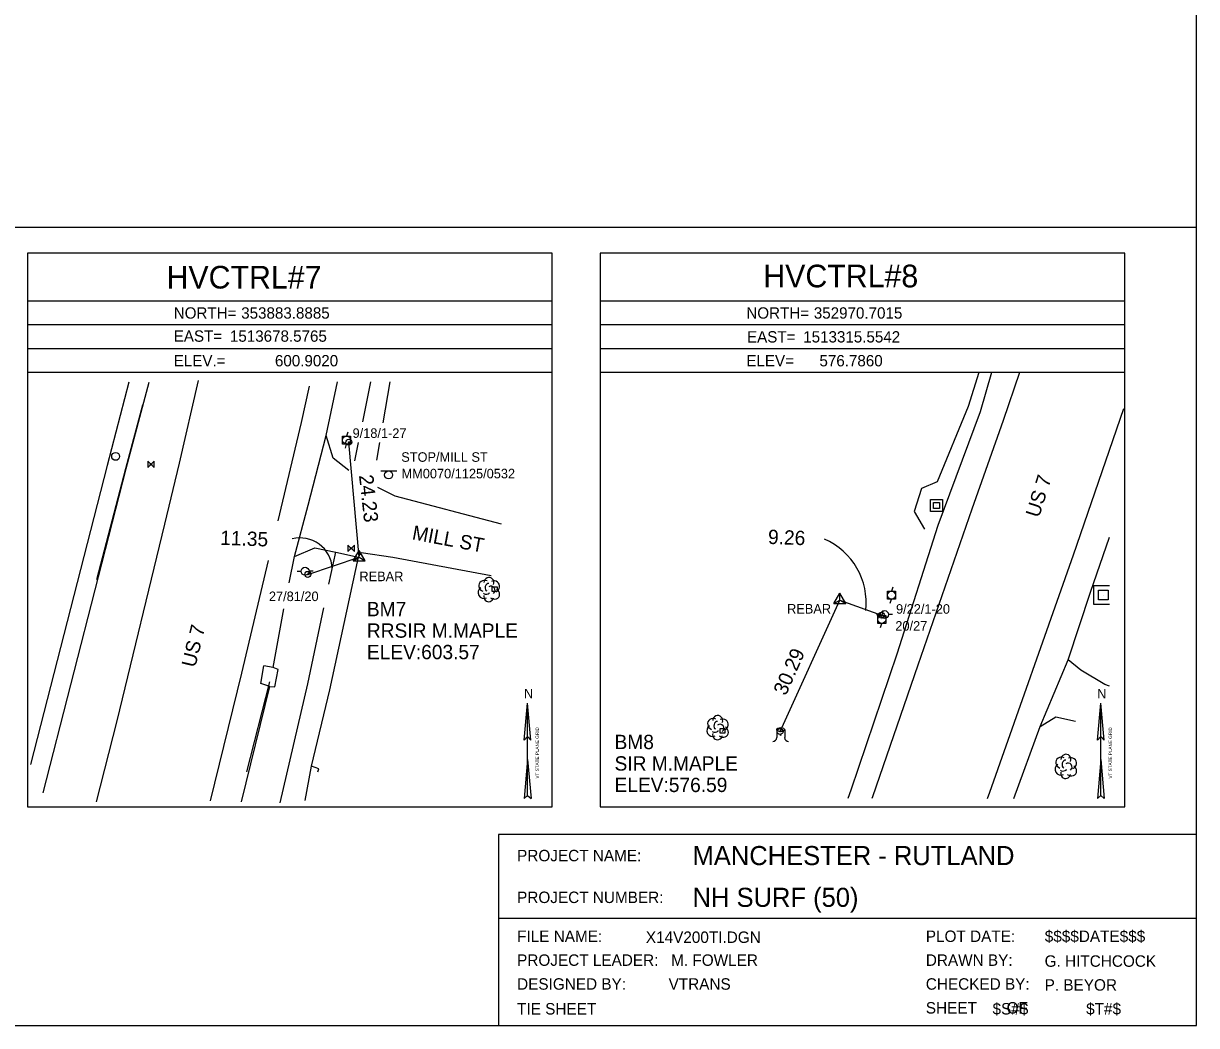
# Model space of a CAD drawing. Extents: x 1514039 to 1514679, y 870735 to 871155.
# Drawn here: x 1514432.7 to 1514678.6, y 870735.2 to 870945.2 of the extents above; entities that cross this region are included whole.
import ezdxf

# ---------------------------------------------------------------- set-up
doc = ezdxf.new("R2010")
doc.units = 0
for name, color, linetype in [('C_A', 7, 'Continuous'), ('CBP', 7, 'Continuous'), ('CPBM', 7, 'Continuous'), ('CPSM', 7, 'Continuous'), ('DCP', 7, 'Continuous'), ('Default', 7, 'Continuous'), ('DS', 7, 'Continuous'), ('LS', 7, 'Continuous'), ('LTD', 7, 'Continuous'), ('LTS', 7, 'Continuous'), ('NBL1', 7, 'Continuous'), ('NBL2', 7, 'Continuous'), ('NNA_P', 7, 'Continuous'), ('PET', 7, 'Continuous'), ('PSP', 7, 'Continuous'), ('RC', 7, 'Continuous'), ('RDP', 7, 'Continuous'), ('RSW', 7, 'Continuous'), ('S_C', 7, 'Continuous'), ('SSGN', 7, 'Continuous'), ('U_C', 7, 'Continuous'), ('UP', 7, 'Continuous'), ('USMH', 7, 'Continuous'), ('UWV', 7, 'Continuous')]:
    doc.layers.add(name, color=color, linetype=linetype)

msp = doc.modelspace()

# ---------------------------------------------------------------- linework, layer by layer
at = {"layer": 'CBP'}
for centre, radius in [((1514500.92, 870857.47), 0.625), ((1514500.92, 870857.47), 0.0833), ((1514492.33, 870829.77), 0.625), ((1514492.33, 870829.77), 0.0833), ((1514612.55, 870821.21), 0.625), ((1514612.55, 870821.21), 0.0833), ((1514591.3, 870796.83), 0.625), ((1514591.3, 870796.83), 0.0833)]:
    msp.add_circle(centre, radius, dxfattribs=at)
at = {"layer": 'CPBM'}
for p, q in [((1514530.99, 870826.15), (1514530.99, 870827.15)), ((1514530.99, 870827.15), (1514531.99, 870827.15)), ((1514531.49, 870826.65), (1514531.49, 870826.65)), ((1514531.49, 870826.65), (1514531.49, 870826.65)), ((1514531.99, 870827.15), (1514531.99, 870826.15)), ((1514531.99, 870826.15), (1514530.99, 870826.15)), ((1514578.75, 870796.49), (1514578.75, 870797.49)), ((1514578.75, 870797.49), (1514579.75, 870797.49)), ((1514579.25, 870796.99), (1514579.25, 870796.99)), ((1514579.25, 870796.99), (1514579.25, 870796.99)), ((1514579.75, 870797.49), (1514579.75, 870796.49)), ((1514579.75, 870796.49), (1514578.75, 870796.49))]:
    msp.add_line(p, q, dxfattribs=at)
at = {"layer": 'CPSM'}
for p, q in [((1514501.84, 870832.62), (1514503.09, 870834.78)), ((1514501.86, 870832.62), (1514503.11, 870834.78)), ((1514504.34, 870832.62), (1514503.09, 870834.78)), ((1514503.09, 870833.34), (1514503.09, 870834.78)), ((1514504.36, 870832.62), (1514503.11, 870834.78)), ((1514503.11, 870833.34), (1514503.11, 870834.78)), ((1514501.84, 870832.62), (1514503.09, 870833.34)), ((1514501.84, 870832.62), (1514504.34, 870832.62)), ((1514501.86, 870832.62), (1514503.11, 870833.34)), ((1514501.86, 870832.62), (1514504.36, 870832.62)), ((1514503.09, 870833.34), (1514503.09, 870833.34)), ((1514503.09, 870833.34), (1514504.34, 870832.62)), ((1514503.11, 870833.34), (1514503.11, 870833.34)), ((1514503.11, 870833.34), (1514504.36, 870832.62)), ((1514602.55, 870823.67), (1514603.8, 870825.83)), ((1514602.55, 870823.67), (1514603.8, 870824.39)), ((1514605.05, 870823.67), (1514603.8, 870825.83)), ((1514603.8, 870824.39), (1514603.8, 870825.83)), ((1514603.8, 870824.39), (1514603.8, 870824.39)), ((1514603.8, 870824.39), (1514605.05, 870823.67)), ((1514602.55, 870823.67), (1514605.05, 870823.67))]:
    msp.add_line(p, q, dxfattribs=at)
at = {"layer": 'DCP'}
msp.add_lwpolyline([(1514479.55, 870788.39), (1514484.38, 870807.27)], dxfattribs=at)
at = {"layer": 'Default'}
for p, q in [((1514503.09, 870833.34), (1514500.92, 870857.47)), ((1514492.33, 870829.77), (1514503.09, 870833.34))]:
    msp.add_line(p, q, dxfattribs=at)
msp.add_lwpolyline([(1514591.3, 870796.83), (1514603.8, 870824.39), (1514612.55, 870821.21)], dxfattribs=at)
for centre, radius, start, end in [((1514490.73, 870830.66), 6.74, 3.3658, 104.3099), ((1514594.77, 870823.79), 14.58, 353.6457, 66.3372)]:
    msp.add_arc(centre, radius, start, end, dxfattribs=at)
at = {"layer": 'DS'}
for p, q in [((1514622.8, 870845.48), (1514625.36, 870845.48)), ((1514622.8, 870842.92), (1514622.8, 870845.48)), ((1514623.44, 870843.56), (1514623.44, 870844.84)), ((1514623.44, 870844.84), (1514624.72, 870844.84)), ((1514624.08, 870844.2), (1514624.08, 870844.2)), ((1514624.08, 870844.2), (1514624.08, 870844.2)), ((1514624.72, 870844.84), (1514624.72, 870843.56)), ((1514625.36, 870845.48), (1514625.36, 870842.92)), ((1514625.36, 870842.92), (1514622.8, 870842.92)), ((1514624.72, 870843.56), (1514623.44, 870843.56)), ((1514657.06, 870827.43), (1514660.32, 870827.43)), ((1514657.06, 870823.43), (1514657.06, 870827.43)), ((1514658.06, 870824.43), (1514658.06, 870826.43)), ((1514658.06, 870826.43), (1514660.06, 870826.43)), ((1514660.06, 870824.43), (1514658.06, 870824.43)), ((1514659.07, 870825.43), (1514659.07, 870825.43)), ((1514659.07, 870825.43), (1514659.07, 870825.43)), ((1514660.06, 870826.43), (1514660.06, 870824.43)), ((1514660.32, 870823.43), (1514657.06, 870823.43))]:
    msp.add_line(p, q, dxfattribs=at)
at = {"layer": 'LS'}
for points in [[(1514484.34, 870806.3), (1514482.45, 870806.89), (1514483.08, 870810.58)], [(1514484.34, 870806.3), (1514485.43, 870806.2), (1514486.09, 870809.85), (1514485.04, 870810.22), (1514483.08, 870810.58)]]:
    msp.add_lwpolyline(points, dxfattribs=at)
at = {"layer": 'LTD'}
for p, q in [((1514530.25, 870826.63), (1514530.25, 870826.63)), ((1514530.25, 870826.63), (1514530.25, 870826.63)), ((1514578.19, 870797.7), (1514578.19, 870797.7)), ((1514578.19, 870797.7), (1514578.19, 870797.7)), ((1514651.16, 870789.58), (1514651.16, 870789.58)), ((1514651.16, 870789.58), (1514651.16, 870789.58))]:
    msp.add_line(p, q, dxfattribs=at)
for centre in [(1514530.3, 870828.06), (1514578.23, 870799.13), (1514651.21, 870791.01)]:
    msp.add_arc(centre, 1.05, 335.5272, 180.9563, dxfattribs=at)
for centre, major_axis, ratio, start_param, end_param in [((1514529.17, 870825.92), (0.58, -1.04), 0.959034, 3.141593, 6.283185), ((1514529.46, 870827.3), (1.21, -0.51), 0.895232, 1.570796, 4.712389), ((1514530.04, 870827.09), (-0.208, -0.792), 0.645439, 3.141593, 6.283185), ((1514530.75, 870826.46), (-0.5, 0.667), 0.989748, 3.141593, 6.283185), ((1514531.25, 870825.8), (-1.09, 0.79), 0.841452, 1.570796, 4.712389), ((1514531.29, 870827.21), (-1.14, -0.48), 0.949671, 1.570796, 4.712389), ((1514530.25, 870825.13), (0.26, 1.06), 0.942809, 1.570796, 4.712389), ((1514529.79, 870825.88), (-0.625, -0.083), 0.423636, 0, 3.141593), ((1514577.4, 870798.37), (1.21, -0.51), 0.895232, 1.570796, 4.712389), ((1514579.23, 870798.28), (-1.14, -0.48), 0.949671, 1.570796, 4.712389), ((1514577.1, 870796.99), (0.58, -1.04), 0.959034, 3.141593, 6.283185), ((1514577.73, 870796.95), (-0.625, -0.083), 0.423636, 0, 3.141593), ((1514577.98, 870798.16), (-0.208, -0.792), 0.645439, 3.141593, 6.283185), ((1514578.69, 870797.53), (-0.5, 0.667), 0.989748, 3.141593, 6.283185), ((1514579.19, 870796.87), (-1.09, 0.79), 0.841452, 1.570796, 4.712389), ((1514578.19, 870796.2), (0.26, 1.06), 0.942809, 1.570796, 4.712389), ((1514650.08, 870788.87), (0.58, -1.04), 0.959034, 3.141593, 6.283185), ((1514650.37, 870790.25), (1.21, -0.51), 0.895232, 1.570796, 4.712389), ((1514650.95, 870790.04), (-0.208, -0.792), 0.645439, 3.141593, 6.283185), ((1514651.66, 870789.41), (-0.5, 0.667), 0.989748, 3.141593, 6.283185), ((1514652.16, 870788.75), (-1.09, 0.79), 0.841452, 1.570796, 4.712389), ((1514652.2, 870790.16), (-1.14, -0.48), 0.949671, 1.570796, 4.712389), ((1514651.16, 870788.08), (0.26, 1.06), 0.942809, 1.570796, 4.712389), ((1514650.7, 870788.83), (-0.625, -0.083), 0.423636, 0, 3.141593)]:
    msp.add_ellipse(centre, major_axis=major_axis, ratio=ratio, start_param=start_param, end_param=end_param, dxfattribs=at)
at = {"layer": 'LTS'}
for p, q in [((1514590.59, 870797.25), (1514590.59, 870795.58)), ((1514592.26, 870797.08), (1514592.26, 870797.25)), ((1514592.26, 870797.25), (1514592.26, 870795.58)), ((1514591.42, 870796.11), (1514591.42, 870796.11)), ((1514591.42, 870796.11), (1514591.42, 870796.11)), ((1514591.42, 870796.08), (1514591.42, 870796.08))]:
    msp.add_line(p, q, dxfattribs=at)
msp.add_circle((1514591.42, 870796.11), 0.0833, dxfattribs=at)
for centre, start, end in [((1514589.76, 870795.58), 270, 360), ((1514593.09, 870795.58), 180, 270)]:
    msp.add_arc(centre, 0.833, start, end, dxfattribs=at)
msp.add_ellipse((1514591.42, 870797.25), major_axis=(-0.833, 0), ratio=0.5, dxfattribs=at)
at = {"layer": 'NBL1'}
msp.add_line((1514532.32, 870757.72), (1514678.57, 870757.72), dxfattribs=at)
msp.add_lwpolyline([(1514038.57, 870735.22), (1514678.57, 870735.22), (1514678.57, 871155.22), (1514038.57, 871155.22)], close=True, dxfattribs=at)
msp.add_lwpolyline([(1514678.57, 870775.22), (1514532.32, 870775.22), (1514532.32, 870735.22)], dxfattribs=at)
at = {"layer": 'NBL2'}
for p, q in [((1514038.57, 870902.55), (1514678.57, 870902.55)), ((1514543.57, 870887.05), (1514433.57, 870887.05)), ((1514663.57, 870887.05), (1514553.57, 870887.05)), ((1514543.57, 870882.05), (1514433.57, 870882.05)), ((1514663.57, 870882.05), (1514553.57, 870882.05)), ((1514439.32, 870877.05), (1514433.57, 870877.05)), ((1514538.96, 870877.05), (1514439.32, 870877.05)), ((1514543.57, 870877.05), (1514538.96, 870877.05)), ((1514663.57, 870877.05), (1514553.57, 870877.05)), ((1514439.32, 870872.05), (1514433.57, 870872.05)), ((1514538.96, 870872.05), (1514439.32, 870872.05)), ((1514543.57, 870872.05), (1514538.96, 870872.05)), ((1514663.57, 870872.05), (1514553.57, 870872.05))]:
    msp.add_line(p, q, dxfattribs=at)
for points in [[(1514433.57, 870781.05), (1514543.57, 870781.05), (1514543.57, 870897.05), (1514433.57, 870897.05)], [(1514553.57, 870781.05), (1514663.57, 870781.05), (1514663.57, 870897.05), (1514553.57, 870897.05)]]:
    msp.add_lwpolyline(points, close=True, dxfattribs=at)
at = {"layer": 'NNA_P'}
for p, q in [((1514537.7, 870795), (1514538.39, 870802.79)), ((1514538.4, 870783.42), (1514538.39, 870802.79)), ((1514539.09, 870795), (1514538.39, 870802.79)), ((1514657.82, 870795), (1514658.51, 870802.79)), ((1514658.51, 870783.42), (1514658.51, 870802.79)), ((1514659.2, 870795), (1514658.51, 870802.79)), ((1514537.7, 870795), (1514538.39, 870795.77)), ((1514539.09, 870795), (1514538.4, 870795.77)), ((1514657.82, 870795), (1514658.51, 870795.77)), ((1514659.21, 870795), (1514658.51, 870795.77)), ((1514538.4, 870790.94), (1514537.68, 870782.78)), ((1514538.39, 870790.94), (1514539.12, 870782.78)), ((1514658.51, 870790.94), (1514657.79, 870782.78)), ((1514658.51, 870790.94), (1514659.23, 870782.78)), ((1514538.4, 870783.42), (1514537.68, 870782.78)), ((1514538.4, 870783.42), (1514539.12, 870782.78)), ((1514658.51, 870783.42), (1514657.79, 870782.78)), ((1514658.51, 870783.42), (1514659.23, 870782.78))]:
    msp.add_line(p, q, dxfattribs=at)
at = {"layer": 'PET'}
for points in [[(1514641.48, 870872.05), (1514638.06, 870861.99), (1514631.48, 870843.43), (1514620.2, 870810.75), (1514610.65, 870783.17), (1514610.51, 870782.78)], [(1514469.34, 870870.39), (1514465.37, 870853.05), (1514462.29, 870840.27), (1514452.33, 870799.08), (1514448, 870782.07)], [(1514486.1, 870840.99), (1514491, 870861.62), (1514492.65, 870869.23)], [(1514634.78, 870782.78), (1514635.24, 870784.12), (1514652.8, 870833.87), (1514663.36, 870864.51)], [(1514500.91, 870851.54), (1514497.61, 870854.14), (1514496.2, 870858.86)], [(1514532.9, 870840.29), (1514510.61, 870846.18), (1514507, 870847.99)], [(1514489.55, 870833.5), (1514493.82, 870835.33), (1514498.17, 870834.4), (1514502.92, 870833.37), (1514503.48, 870834.32), (1514510.12, 870833.36), (1514530.78, 870829.55)], [(1514471.94, 870782.29), (1514478.51, 870809.08), (1514484.11, 870832.65)]]:
    msp.add_lwpolyline(points, dxfattribs=at)
at = {"layer": 'PSP'}
for points in [[(1514635.59, 870872.05), (1514633.2, 870863.82), (1514624.33, 870840.01), (1514615.78, 870813.05), (1514606.12, 870784.54), (1514605.49, 870782.78)], [(1514458.98, 870869.97), (1514454.22, 870851.89), (1514436.8, 870784.02)], [(1514488.41, 870828.02), (1514489.55, 870833.5), (1514492.37, 870844.26), (1514496.2, 870858.86), (1514498.54, 870870.12)], [(1514640.27, 870782.78), (1514645.82, 870797.91), (1514651.66, 870811.88), (1514656.32, 870826.07), (1514660.32, 870837.58)], [(1514485.04, 870810.22), (1514487.27, 870822.54)], [(1514478.44, 870782.1), (1514484.34, 870806.3)]]:
    msp.add_lwpolyline(points, dxfattribs=at)
at = {"layer": 'RC'}
msp.add_lwpolyline([(1514632.96, 870872.05), (1514630.72, 870864.92), (1514624.22, 870849.14), (1514620.94, 870847.79), (1514619.4, 870842.92), (1514621.59, 870839.22)], dxfattribs=at)
at = {"layer": 'RDP'}
for points in [[(1514660.32, 870806.36), (1514659.38, 870806.69), (1514654.33, 870809.7), (1514651.66, 870811.88)], [(1514645.82, 870797.91), (1514649.11, 870799.89), (1514653.24, 870798.98)]]:
    msp.add_lwpolyline(points, dxfattribs=at)
at = {"layer": 'RSW'}
for points in [[(1514454.8, 870870.05), (1514450.28, 870852.59), (1514434.2, 870789.93)], [(1514503.85, 870861.75), (1514505.57, 870870.11)], [(1514508.11, 870861.53), (1514509.57, 870870.11)], [(1514457.66, 870865.21), (1514454.09, 870851.92), (1514448.04, 870828.6)], [(1514502.16, 870853.59), (1514502.95, 870857.4)], [(1514506.77, 870853.71), (1514507.4, 870857.43)], [(1514496.75, 870827.71), (1514498.17, 870834.4)], [(1514491.78, 870782.37), (1514493.09, 870789.58), (1514496.97, 870805.6), (1514502.92, 870833.37)], [(1514486.55, 870781.89), (1514492.32, 870806.82), (1514495.69, 870822.74)], [(1514494.4, 870788.39), (1514494.61, 870789), (1514493.09, 870789.58)]]:
    msp.add_lwpolyline(points, dxfattribs=at)
at = {"layer": 'SSGN'}
for p, q in [((1514507.62, 870851.44), (1514510.95, 870851.44)), ((1514509.26, 870850.61), (1514509.26, 870850.61))]:
    msp.add_line(p, q, dxfattribs=at)
msp.add_circle((1514509.26, 870850.61), 0.833, dxfattribs=at)
at = {"layer": 'UP'}
for p, q in [((1514499.62, 870857.06), (1514499.62, 870858.73)), ((1514499.62, 870858.73), (1514501.29, 870858.73)), ((1514500.71, 870859.56), (1514500.46, 870858.73)), ((1514501.29, 870858.73), (1514501.29, 870857.06)), ((1514501.29, 870857.06), (1514499.62, 870857.06)), ((1514500.21, 870856.23), (1514500.46, 870857.06)), ((1514500.46, 870857.9), (1514500.46, 870857.9)), ((1514490.09, 870830.42), (1514490.92, 870830.42)), ((1514491.75, 870830.42), (1514491.75, 870830.42)), ((1514493.42, 870830.42), (1514492.58, 870830.42)), ((1514492.58, 870830.42), (1514492.58, 870830.42)), ((1514493.42, 870830.42), (1514493.42, 870830.42)), ((1514614.9, 870827.06), (1514614.65, 870826.22)), ((1514613.82, 870824.56), (1514613.82, 870826.22)), ((1514613.82, 870826.22), (1514615.49, 870826.22)), ((1514615.49, 870824.56), (1514613.82, 870824.56)), ((1514614.4, 870823.72), (1514614.65, 870824.56)), ((1514614.65, 870825.39), (1514614.65, 870825.39)), ((1514615.49, 870826.22), (1514615.49, 870824.56)), ((1514612.86, 870821.98), (1514612.61, 870821.15)), ((1514611.52, 870821.35), (1514612.35, 870821.35)), ((1514611.78, 870819.48), (1514611.78, 870821.15)), ((1514611.78, 870821.15), (1514613.45, 870821.15)), ((1514613.45, 870819.48), (1514611.78, 870819.48)), ((1514612.36, 870818.65), (1514612.61, 870819.48)), ((1514612.61, 870820.32), (1514612.61, 870820.32)), ((1514613.18, 870821.35), (1514613.18, 870821.35)), ((1514613.45, 870821.15), (1514613.45, 870819.48)), ((1514614.85, 870821.35), (1514614.01, 870821.35)), ((1514614.01, 870821.35), (1514614.01, 870821.35)), ((1514614.85, 870821.35), (1514614.85, 870821.35))]:
    msp.add_line(p, q, dxfattribs=at)
for centre in [(1514500.46, 870857.9), (1514491.75, 870830.42), (1514614.65, 870825.39), (1514613.18, 870821.35), (1514612.61, 870820.32)]:
    msp.add_circle(centre, 0.833, dxfattribs=at)
at = {"layer": 'USMH'}
for p, q in [((1514452.06, 870854.5), (1514452.06, 870854.5)), ((1514452.89, 870854.5), (1514452.89, 870854.5))]:
    msp.add_line(p, q, dxfattribs=at)
msp.add_circle((1514452.06, 870854.5), 0.833, dxfattribs=at)
at = {"layer": 'UWV'}
for p, q in [((1514458.8, 870853.47), (1514460.14, 870852.14)), ((1514460.14, 870853.47), (1514458.8, 870852.14)), ((1514500.75, 870835.88), (1514502.08, 870834.55)), ((1514502.08, 870835.88), (1514500.75, 870834.55))]:
    msp.add_line(p, q, dxfattribs=at)
for points in [[(1514458.8, 870853.47), (1514458.8, 870852.14)], [(1514460.14, 870852.14), (1514460.14, 870853.47)], [(1514500.75, 870835.88), (1514500.75, 870834.55)], [(1514502.08, 870834.55), (1514502.08, 870835.88)]]:
    msp.add_lwpolyline(points, dxfattribs=at)
for centre in [(1514459.47, 870852.81), (1514501.42, 870835.22)]:
    msp.add_circle(centre, 0.167, dxfattribs=at)

# ---------------------------------------------------------------- texts
at = {"layer": 'C_A'}
for p in [(1514503.14, 870828.34), (1514592.77, 870821.55)]:
    msp.add_text('REBAR', height=2, dxfattribs=at).set_placement(p)
at = {"layer": 'Default'}
for s, rotation, p in [('24.23', 276.4476, (1514503.04, 870850.5)), ('US 7', 72.4885, (1514645.55, 870841.5)), ('11.35', 357.9012, (1514473.93, 870835.97)), ('MILL ST', 349.3312, (1514514.04, 870837.13)), ('9.26', 357.9012, (1514588.73, 870836.16)), ('BM7', 360, (1514504.71, 870820.99)), ('US 7', 76.2021, (1514468.74, 870810.11)), ('RRSIR M.MAPLE', 360, (1514504.71, 870816.49)), ('ELEV:603.57', 360, (1514504.71, 870811.99)), ('30.29', 66.1125, (1514592.51, 870804.21)), ('BM8', 360, (1514556.61, 870793.15)), ('SIR M.MAPLE', 360, (1514556.61, 870788.65)), ('ELEV:576.59', 360, (1514556.61, 870784.15))]:
    msp.add_text(s, height=3, rotation=rotation, dxfattribs=at).set_placement(p)
at = {"layer": 'NBL1'}
for s, height, p in [('MANCHESTER - RUTLAND ', 4, (1514572.96, 870768.84)), ('PROJECT NAME:', 2.4, (1514536.19, 870769.64)), ('PROJECT NUMBER:', 2.4, (1514536.19, 870760.89)), ('NH SURF (50)', 4, (1514572.96, 870760.09)), ('PLOT DATE:', 2.4, (1514621.84, 870752.73)), ('$$$$DATE$$$', 2.4, (1514646.77, 870752.73)), ('FILE NAME:', 2.4, (1514536.19, 870752.73)), ('      X14V200TI.DGN', 2.4, (1514557.82, 870752.53)), ('PROJECT LEADER:   M. FOWLER ', 2.4, (1514536.19, 870747.73)), ('DRAWN BY:', 2.4, (1514621.84, 870747.73)), ('G. HITCHCOCK', 2.4, (1514646.74, 870747.53)), ('DESIGNED BY:          VTRANS', 2.4, (1514536.19, 870742.73)), ('CHECKED BY:', 2.4, (1514621.84, 870742.73)), ('P. BEYOR', 2.4, (1514646.74, 870742.53)), ('TIE SHEET ', 2.4, (1514536.19, 870737.53)), ('SHEET       OF', 2.4, (1514621.84, 870737.73)), ('$S#$ ', 2.4, (1514635.82, 870737.53)), ('$T#$   ', 2.4, (1514655.44, 870737.53))]:
    msp.add_text(s, height=height, dxfattribs=at).set_placement(p)
at = {"layer": 'NBL2'}
for s, height, p in [('HVCTRL#7', 4.75, (1514462.72, 870889.67)), ('HVCTRL#8', 4.75, (1514587.78, 870889.92)), ('NORTH=', 2.375, (1514464.23, 870883.36)), ('353883.8885', 2.375, (1514478.37, 870883.36)), ('NORTH=', 2.375, (1514584.23, 870883.36)), ('352970.7015', 2.375, (1514598.37, 870883.36)), ('EAST=', 2.375, (1514464.23, 870878.52)), ('1513678.5765', 2.375, (1514476.01, 870878.52)), ('EAST=', 2.375, (1514584.37, 870878.36)), ('1513315.5542', 2.375, (1514596.15, 870878.36)), ('ELEV.=   ', 2.375, (1514464.23, 870873.36)), ('600.9020', 2.375, (1514485.44, 870873.36)), ('ELEV=', 2.375, (1514584.23, 870873.36)), ('    576.7860', 2.375, (1514596.02, 870873.36))]:
    msp.add_text(s, height=height, dxfattribs=at).set_placement(p)
at = {"layer": 'NNA_P'}
for p in [(1514537.63, 870803.81), (1514657.75, 870803.81)]:
    msp.add_text('N', height=1.97, dxfattribs=at).set_placement(p)
for p in [(1514540.75, 870786.98), (1514660.86, 870786.98)]:
    msp.add_text('VT STATE PLANE GRID', height=0.7, rotation=90.0204, dxfattribs=at).set_placement(p)
at = {"layer": 'S_C'}
for s, p in [('STOP/MILL ST', (1514511.91, 870853.36)), ('MM0070/1125/0532', (1514511.97, 870849.89))]:
    msp.add_text(s, height=2, dxfattribs=at).set_placement(p)
at = {"layer": 'U_C'}
for s, p in [('9/18/1-27', (1514501.71, 870858.37)), ('27/81/20', (1514484.18, 870824.17)), ('9/22/1-20', (1514615.6, 870821.52)), ('20/27', (1514615.45, 870817.97))]:
    msp.add_text(s, height=2, dxfattribs=at).set_placement(p)

doc.saveas('drawing.dxf')
